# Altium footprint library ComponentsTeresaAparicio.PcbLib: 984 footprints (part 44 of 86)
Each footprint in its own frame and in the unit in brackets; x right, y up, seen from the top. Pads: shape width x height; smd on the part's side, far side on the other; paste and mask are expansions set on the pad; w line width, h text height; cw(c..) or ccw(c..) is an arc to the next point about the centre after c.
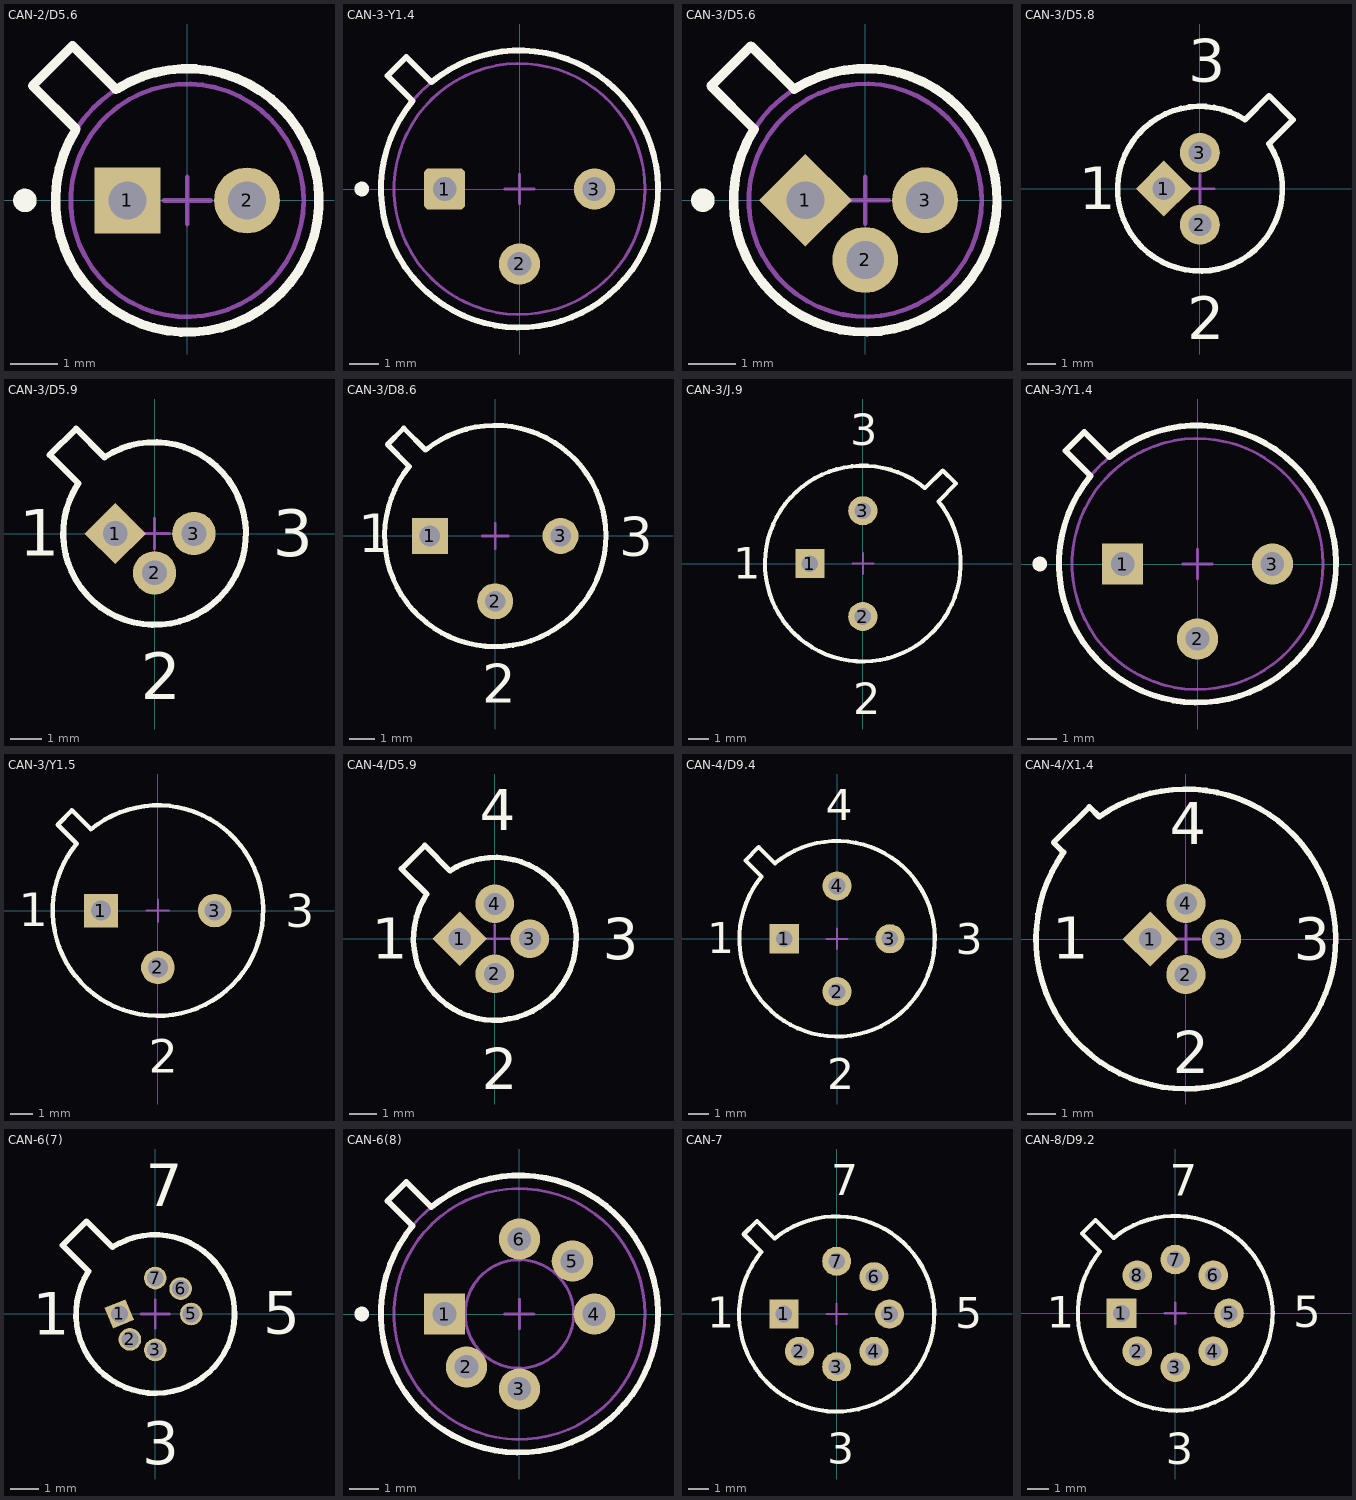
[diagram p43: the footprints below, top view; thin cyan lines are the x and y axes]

## CAN-2/D5.6 [mm] "Can; 2 Leads; Pin Circle Dia. 2.54 mm; Lead Dia. 0.48 mm (max)"
height 2.67
pads (2):
  rect 1.4x1.4 hole 0.8: 1(-1.27,0)
  round 1.4 hole 0.8: 2(1.27,0)
Top Overlay:
  circle w0.25: c-3.45,0 r0.125
  lines w0.2: -2.375,1.484 ccw(c0,0) -1.484,2.375 ; -2.367,1.518 -3.286,2.437 -2.437,3.286 -1.518,2.367
Mechanical 13:
  circle w0.1: c0,0 r2.475
  circle w0.1: c0,0 r2.8
Mechanical 15:
  lines w0.1: -0.5,0 0.5,0 ; 0,-0.5 0,0.5
3D body: height 2.67, standoff 0.76, extent -2.486,-2.486 2.486,2.486
3D body: height 0.76, standoff 0, extent -2.808,-2.808 2.808,2.808

## CAN-3-Y1.4 [mm] "Can; 3 Leads; Pin Circle Dia. 5.08 mm; Lead Dia. 0.48 mm (max)"
height 4.55
pads (3):
  rrect25% 1.4x1.4 hole 0.8: 1(-2.54,0)
  round 1.4 hole 0.8: 2(0,-2.54) 3(2.54,0)
Top Overlay:
  circle w0.25: c-5.35,0 r0.125
  lines w0.2: -3.626,2.99 -4.475,3.838 -3.838,4.475 -2.99,3.626 ; -3.622,2.987 ccw(c0,0) -2.987,3.622
Mechanical 13:
  circle w0.1: c0,0 r4.695
  circle w0.1: c0,0 r4.255
Mechanical 14:
  lines w0.1: -0.5,0 0.5,0 ; 0,-0.5 0,0.5
3D body: height 1.27, standoff 0, extent -4.705,-4.705 4.705,4.705
3D body: height 4.55, standoff 1.27, extent -4.264,-4.264 4.264,4.264

## CAN-3/D5.6 [mm] "Can; 3 Leads; Pin Circle Dia. 2.54 mm; Lead Dia. 0.48 mm (max)"
height 2.67
pads (3):
  rect 1.4x1.4 hole 0.8 rot 45: 1(-1.27,0)
  round 1.4 hole 0.8: 2(0,-1.27) 3(1.27,0)
Top Overlay:
  circle w0.25: c-3.45,0 r0.125
  lines w0.2: -3.277,2.429 -2.358,1.51 ccw(c0,0) -1.51,2.358 -2.429,3.277 -3.277,2.429
Mechanical 13:
  circle w0.1: c0,0 r2.8
  circle w0.1: c0,0 r2.475
Mechanical 15:
  lines w0.1: -0.5,0 0.5,0 ; 0,-0.5 0,0.5
3D body: height 0.76, standoff 0, extent -2.808,-2.808 2.808,2.808
3D body: height 2.67, standoff 0.76, extent -2.486,-2.486 2.486,2.486

## CAN-3/D5.8 [mm] "Can; 3 Leads; Pin Circle Dia. 2.54 mm; Lead Dia. 0.49 mm (max)"
height 5.3
pads (3):
  rect 1.4x1.4 hole 0.8 rot 45: 1(-1.27,0)
  round 1.4 hole 0.8: 2(0,-1.27) 3(0,1.27)
Top Overlay:
  lines w0.2: 1.582,2.431 ccw(c0,0) 2.431,1.582 3.279,2.431 2.431,3.279 1.582,2.431
  text "3" at -0.419,3.772 h1.5
  text "2" at -0.443,-5.291 h1.5
  text "1" at -4.262,-0.718 h1.5
Mechanical 15:
  lines w0.1: -0.5,0 0.5,0 ; 0,-0.5 0,0.5

## CAN-3/D5.9 [mm] "Can; 3 Leads; Pin Circle Dia. 2.54 mm; Lead Dia. 0.48 mm (max)"
height 3.81
pads (3):
  rect 1.4x1.4 hole 0.8 rot 45: 1(-1.27,0)
  round 1.4 hole 0.8: 2(0,-1.27) 3(1.27,0)
Top Overlay:
  lines w0.2: -3.386,2.537 -2.467,1.618 ccw(c0,0) -1.618,2.467 -2.537,3.386 -3.386,2.537
  text "3" at 3.812,-0.742 h1.5
  text "2" at -0.443,-5.355 h1.5
  text "1" at -4.38,-0.719 h1.5
Mechanical 15:
  lines w0.1: -0.5,0 0.5,0 ; 0,-0.5 0,0.5

## CAN-3/D8.6 [mm] "Can; 3 Leads; Pin Circle Dia. 5.08 mm; Lead Dia. 0.48 mm (max)"
height 4.7
pads (3):
  rect 1.4x1.4 hole 0.8: 1(-2.54,0)
  round 1.4 hole 0.8: 2(0,-2.54) 3(2.54,0)
Top Overlay:
  lines w0.2: -4.191,3.554 -3.342,2.706 ccw(c0,0) -2.706,3.342 -3.554,4.19 -4.19,3.554
  text "3" at 4.826,-0.762 h1.5
  text "2" at -0.508,-6.477 h1.5
  text "1" at -5.334,-0.635 h1.5
Mechanical 15:
  lines w0.1: -0.5,0 0.5,0 ; 0,-0.5 0,0.5

## CAN-3/J.9 [mm] "Can; 3 Leads; Pin Circle Dia. 5.08 mm; Lead Dia. 0.49 mm (max)"
height 6.6
pads (3):
  rect 1.4x1.4 hole 0.8: 1(-2.54,0)
  round 1.4 hole 0.8: 2(0,-2.54) 3(0,2.54)
Top Overlay:
  lines w0.2: 2.99,3.626 ccw(c0,0) 3.626,2.99 4.475,3.838 3.838,4.475 2.99,3.626
  text "3" at -0.595,5.683 h1.5
  text "2" at -0.469,-7.22 h1.5
  text "1" at -6.219,-0.733 h1.5
Mechanical 15:
  lines w0.1: -0.5,0 0.5,0 ; 0,-0.5 0,0.5

## CAN-3/Y1.4 [mm] "Can; 3 Leads; Pin Circle Dia. 5.08 mm; Lead Dia. 0.48 mm (max)"
height 4.7
pads (3):
  rect 1.4x1.4 hole 0.8: 1(-2.54,0)
  round 1.4 hole 0.8: 2(0,-2.54) 3(2.54,0)
Top Overlay:
  circle w0.25: c-5.35,0 r0.125
  lines w0.2: -3.626,2.99 -4.475,3.838 -3.838,4.475 -2.99,3.626 ; -3.622,2.987 ccw(c0,0) -2.987,3.622
Mechanical 13:
  circle w0.1: c0,0 r4.695
  circle w0.1: c0,0 r4.255
Mechanical 15:
  lines w0.1: -0.5,0 0.5,0 ; 0,-0.5 0,0.5
3D body: height 1.27, standoff 0, extent -4.705,-4.705 4.705,4.705
3D body: height 4.7, standoff 1.27, extent -4.264,-4.264 4.264,4.264

## CAN-3/Y1.5 [mm] "Can; 3 Leads; Pin Circle Dia. 5.08 mm; Lead Dia. 0.53 mm (max)"
height 4.57
pads (3):
  rect 1.5x1.5 hole 0.9: 1(-2.54,0)
  round 1.5 hole 0.9: 2(0,-2.54) 3(2.54,0)
Top Overlay:
  lines w0.2: -4.475,3.838 -3.626,2.99 ccw(c0,0) -2.99,3.626 -3.838,4.475 -4.475,3.838
  text "1" at -6.201,-0.697 h1.5
  text "2" at -0.415,-7.238 h1.5
  text "3" at 5.694,-0.751 h1.5
Mechanical 15:
  lines w0.1: -0.5,0 0.5,0 ; 0,-0.5 0,0.5

## CAN-4/D5.9 [mm] "Can; 4 Leads; Pin Circle Dia. 2.54 mm; Lead Dia. 0.48 mm (max)"
height 5.34
pads (4):
  rect 1.4x1.4 hole 0.8 rot 45: 1(-1.27,0)
  round 1.4 hole 0.8: 2(0,-1.27) 3(1.27,0) 4(0,1.27)
Top Overlay:
  lines w0.2: -3.386,2.537 -2.467,1.618 ccw(c0,0) -1.618,2.467 -2.537,3.386 -3.386,2.537
  text "1" at -4.454,-0.719 h1.5
  text "2" at -0.468,-5.441 h1.5
  text "3" at 3.91,-0.743 h1.5
  text "4" at -0.554,3.93 h1.5
Mechanical 15:
  lines w0.1: -0.5,0 0.5,0 ; 0,-0.5 0,0.5

## CAN-4/D9.4 [mm] "Can; 4 Leads; Pin Circle Dia. 5.08 mm; Lead Dia. 0.48 mm (max)"
height 4.7
pads (4):
  rect 1.4x1.4 hole 0.8: 1(-2.54,0)
  round 1.4 hole 0.8: 2(0,-2.54) 3(2.54,0) 4(0,2.54)
Top Overlay:
  lines w0.2: -4.404,3.768 -3.626,2.99 ccw(c0,0) -2.99,3.626 -3.768,4.404 -4.404,3.768
  text "4" at -0.541,5.701 h1.5
  text "3" at 5.694,-0.751 h1.5
  text "2" at -0.469,-7.221 h1.5
  text "1" at -6.238,-0.697 h1.5
Mechanical 15:
  lines w0.1: -0.5,0 0.5,0 ; 0,-0.5 0,0.5

## CAN-4/X1.4 [mm] "Can; 4 Leads; Pin Circle Dia. 2.54 mm; Lead Dia. 0.48 mm (max)"
height 5.95
pads (4):
  rect 1.4x1.4 hole 0.8 rot 45: 1(-1.27,0)
  round 1.4 hole 0.8: 2(0,-1.27) 3(1.27,0) 4(0,1.27)
Top Overlay:
  lines w0.2: -4.719,3.446 -3.446,4.719 -3.093,4.366 cw(c0,0) -4.366,3.093 -4.719,3.446
  text "4" at -0.57,3.375 h1.5
  text "3" at 3.86,-0.743 h1.5
  text "2" at -0.47,-4.8 h1.5
  text "1" at -4.77,-0.7 h1.5
Mechanical 15:
  lines w0.1: -0.5,0 0.5,0 ; 0,-0.5 0,0.5

## CAN-6(7) [mm] "Can; 7 Leads (1 Absent); Pin Circle Dia. 2.54 mm; Lead Dia. 0.48 mm (max)"
height 5.34
pads (6):
  rect 0.8x0.8 hole 0.6 rot 22.5: 1(-1.27,0)
  round 0.8 hole 0.6: 2(-0.898,-0.898) 3(0,-1.27) 5(1.27,0) 6(0.898,0.898) 7(0,1.27)
Top Overlay:
  lines w0.2: -3.277,2.429 -2.358,1.51 ccw(c0,0) -1.51,2.358 -2.429,3.277 -3.277,2.429
  text "7" at -0.336,3.798 h1.5
  text "5" at 3.806,-0.692 h1.5
  text "3" at -0.465,-5.299 h1.5
  text "1" at -4.335,-0.727 h1.5
Mechanical 15:
  lines w0.1: -0.5,0 0.5,0 ; 0,-0.5 0,0.5

## CAN-6(8) [mm] "Can; 8 Leads (2 Absent); Pin Circle Dia. 5.08 mm; Lead Dia. 0.48 mm (max)"
height 5.56
pads (6):
  rect 1.4x1.4 hole 0.8: 1(-2.54,0)
  round 1.4 hole 0.8: 2(-1.796,-1.796) 3(0,-2.54) 4(2.54,0) 5(1.796,1.796) 6(0,2.54)
Top Overlay:
  circle w0.25: c-5.35,0 r0.125
  lines w0.2: -4.475,3.838 -3.838,4.475 -2.99,3.626 cw(c0,0) -3.626,2.99 -4.475,3.838
Mechanical 13:
  circle w0.1: c0,0 r1.84
  circle w0.1: c0,0 r4.7
  circle w0.1: c0,0 r4.255
Mechanical 15:
  lines w0.1: -0.5,0 0.5,0 ; 0,-0.5 0,0.5
3D body: height 1.91, standoff 0.38, extent -4.71,-4.71 4.71,4.71
3D body: height 5.56, standoff 1.91, extent -4.264,-4.264 4.264,4.264
3D body: height 0.38, standoff 0, extent -1.848,-1.848 1.848,1.848

## CAN-7 [mm] "Can; 7 Leads; Pin Circle Dia. 5.08 mm; Lead Dia. 0.48 mm (max)"
height 4.7
pads (7):
  rect 1.4x1.4 hole 0.8: 1(-2.54,0)
  round 1.4 hole 0.8: 2(-1.796,-1.796) 3(0,-2.54) 4(1.796,-1.796) 5(2.54,0) 6(1.796,1.796) 7(0,2.54)
Top Overlay:
  lines w0.2: -4.475,3.838 -3.838,4.475 -2.99,3.626 cw(c0,0) -3.626,2.99 -4.475,3.838
  text "1" at -6.22,-0.661 h1.5
  text "3" at -0.451,-7.22 h1.5
  text "5" at 5.713,-0.697 h1.5
  text "7" at -0.254,5.719 h1.5
Mechanical 15:
  lines w0.1: -0.5,0 0.5,0 ; 0,-0.5 0,0.5

## CAN-8/D9.2 [mm] "Can; 8 Leads; Pin Circle Dia. 5.08 mm; Lead Dia. 0.48 mm (max)"
height 6.6
pads (8):
  rect 1.4x1.4 hole 0.8: 1(-2.54,0)
  round 1.4 hole 0.8: 2(-1.796,-1.796) 3(0,-2.54) 4(1.796,-1.796) 5(2.54,0) 6(1.796,1.796) 7(0,2.54) 8(-1.796,1.796)
Top Overlay:
  lines w0.2: -4.404,3.767 -3.767,4.404 -2.919,3.555 cw(c0,0) -3.555,2.919 -4.404,3.767
  text "7" at -0.261,5.552 h1.5
  text "5" at 5.582,-0.66 h1.5
  text "3" at -0.455,-7.118 h1.5
  text "1" at -6.067,-0.678 h1.5
Mechanical 15:
  lines w0.1: -0.5,0 0.5,0 ; 0,-0.5 0,0.5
